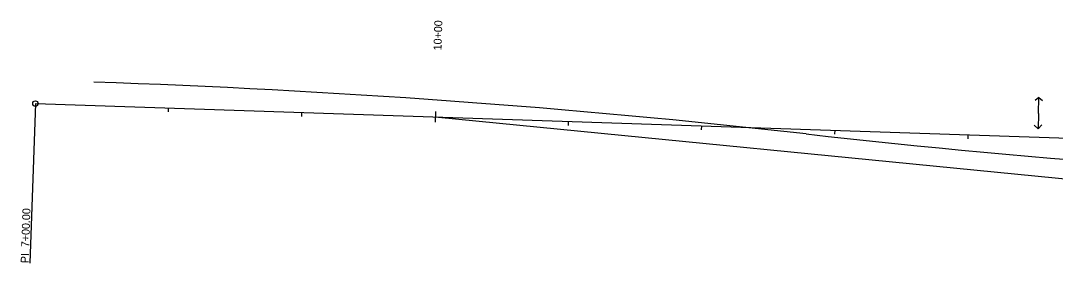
# Model space of a CAD drawing. Extents: x 976639 to 985448, y 1524031 to 1526806.
# Drawn here: x 976639 to 977415, y 1526404 to 1526586 of the extents above; entities that cross this region are included whole.
import ezdxf

# ---------------------------------------------------------------- set-up
doc = ezdxf.new("R2010")
doc.units = 0
for name, color, linetype in [('R_Horz Alg', 7, 'Continuous'), ('R_Horz Alg Annot', 7, 'Continuous'), ('R_Proposed Road_Lane', 7, 'Continuous'), ('R_Proposed Road_Shoulder', 7, 'Continuous'), ('S_WORKING_LINES', 7, 'Continuous')]:
    doc.layers.add(name, color=color, linetype=linetype)

msp = doc.modelspace()

# ---------------------------------------------------------------- linework, layer by layer
at = {"layer": 'R_Horz Alg'}
msp.add_line((976649.79, 1526523.99), (979428.24, 1526431.1), dxfattribs=at)
at = {"layer": 'R_Horz Alg Annot'}
for points in [[(976649.79, 1526523.99), (976645.78, 1526404.06)], [(976749.63, 1526517.65), (976749.73, 1526520.65)], [(976849.58, 1526514.31), (976849.68, 1526517.31)], [(976949.76, 1526517.96), (976949.49, 1526509.97)], [(977049.47, 1526507.63), (977049.57, 1526510.62)], [(977149.41, 1526504.28), (977149.51, 1526507.28)], [(977249.35, 1526500.94), (977249.45, 1526503.94)], [(977349.3, 1526497.6), (977349.4, 1526500.6)]]:
    msp.add_lwpolyline(points, dxfattribs=at)
msp.add_circle((976649.79, 1526523.99), 2, dxfattribs=at)
at = {"layer": 'R_Proposed Road_Lane'}
for p, q in [((977402.37, 1526528.58), (977399.53, 1526526.27)), ((977402.06, 1526516.56), (977402.37, 1526528.58)), ((977402.37, 1526528.58), (977404.92, 1526526.4)), ((977402.06, 1526516.56), (977401.76, 1526505.02)), ((977401.76, 1526505.02), (977398.76, 1526507.82)), ((977398.76, 1526507.82), (977401.76, 1526505.02)), ((977401.76, 1526505.02), (977404.56, 1526508.02))]:
    msp.add_line(p, q, dxfattribs=at)
at = {"layer": 'R_Proposed Road_Shoulder'}
msp.add_line((977523.05, 1526457.27), (976949.61, 1526513.71), dxfattribs=at)
at = {"layer": 'S_WORKING_LINES'}
msp.add_line((976649.79, 1526523.99), (979428.24, 1526431.1), dxfattribs=at)
for centre, start, end in [((976465.34, 1519713.85), 83.591075, 88.085232), ((977990.12, 1533288.48), 263.591075, 268.085232)]:
    msp.add_arc(centre, 6830, start, end, dxfattribs=at)

# ---------------------------------------------------------------- texts
at = {"layer": 'R_Horz Alg Annot'}
for s, p in [('10+00', (976954.29, 1526563.84)), ('PI  7+00.00', (976644.78, 1526404.09))]:
    msp.add_text(s, height=6, rotation=88.08523, dxfattribs=at).set_placement(p)

doc.saveas('drawing.dxf')
